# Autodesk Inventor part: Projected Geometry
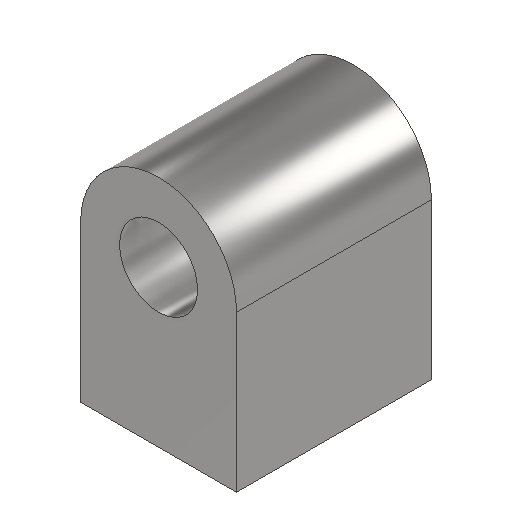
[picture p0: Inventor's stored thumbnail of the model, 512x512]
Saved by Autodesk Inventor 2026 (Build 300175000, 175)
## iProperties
Created: 2022-01
Part Number: Projected Geometry
Material: Steel, Mild
Document SubType Name: Modeling
Designer: Lars Bertram Pedersen
Density: 7.85 g/cm^3
Appearance: Semi-Polished
Author: Lars Bertram Pedersen
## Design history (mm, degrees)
sketch "Sketch1"
  geometry: L1 (-10, 0)-(10, 0); L2 (10, 0)-(10, 20); L3 (-10, 20)-(-10, 0); C1 r 5 at (0, 20); A1 r 10 centre (0, 20) between (10, 20) and (-10, 20); 2 further points
  constraints: 6 end point, 2 centre point, 2 coincident, 2 point on circle, 2 tangent, 1 horizontal, 1 midpoint, 1 parallel, 1 perpendicular
  dimensions: "d0" = 20 distance of L1.start L1.end; "d1" = 20 distance of point (0, 0) A1.centre; "d2" = 10 diameter of C1
extrude "Extrusion1" new body sketch "Sketch1" distance "d3" = 25; taper "d4" = 0 deg
body "Solid1"
